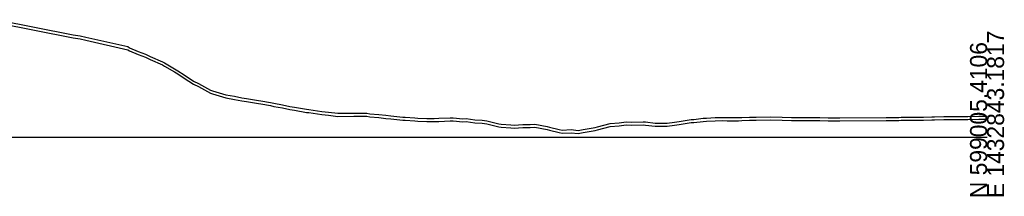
# Model space of a CAD drawing. Extents: x -26 to 2203, y -10 to 12201.
# Drawn here: x 440.9 to 602.8, y 9990.3 to 10019.3 of the extents above; entities that cross this region are included whole.
import ezdxf

# ---------------------------------------------------------------- set-up
doc = ezdxf.new("R2010")
doc.units = 0
for name, color, linetype in [('DESIGN - SHEET - Light Grid', 7, 'Continuous'), ('SURVEY - GROUND - Bottom of Topsoil Layer', 7, 'Continuous'), ('SURVEY - GROUND - Top of Ground', 7, 'Continuous')]:
    doc.layers.add(name, color=color, linetype=linetype)

msp = doc.modelspace()

# ---------------------------------------------------------------- linework, layer by layer
at = {"layer": 'DESIGN - SHEET - Light Grid'}
msp.add_line((300, 10000), (600, 10000), dxfattribs=at)
at = {"layer": 'SURVEY - GROUND - Bottom of Topsoil Layer'}
for p, q in [((437.07, 10018.78), (449.69, 10016.3)), ((449.69, 10016.3), (450.87, 10016.16)), ((450.87, 10016.16), (451.82, 10015.93)), ((451.82, 10015.93), (458.68, 10014.36)), ((458.68, 10014.36), (458.99, 10014.15)), ((458.99, 10014.15), (460.43, 10013.57)), ((460.43, 10013.57), (461.63, 10013.15)), ((461.63, 10013.15), (462.4, 10012.73)), ((462.4, 10012.73), (464.38, 10011.88)), ((464.38, 10011.88), (464.73, 10011.68)), ((464.73, 10011.68), (466.36, 10010.72)), ((466.36, 10010.72), (466.9, 10010.39)), ((466.9, 10010.39), (467.98, 10009.71)), ((467.98, 10009.71), (469.53, 10008.72)), ((469.53, 10008.72), (470.31, 10008.31)), ((470.31, 10008.31), (472.29, 10007.2)), ((472.29, 10007.2), (472.64, 10007.09)), ((472.64, 10007.09), (474.26, 10006.63)), ((474.26, 10006.63), (474.8, 10006.45)), ((474.8, 10006.45), (476.24, 10006.21)), ((476.24, 10006.21), (477.44, 10005.98)), ((477.44, 10005.98), (478.22, 10005.87)), ((478.22, 10005.87), (480.19, 10005.55)), ((480.19, 10005.55), (480.56, 10005.47)), ((480.56, 10005.47), (482.17, 10005.19)), ((482.17, 10005.19), (482.71, 10005.06)), ((482.71, 10005.06), (484.15, 10004.81)), ((484.15, 10004.81), (485.34, 10004.54)), ((485.34, 10004.54), (486.12, 10004.43)), ((486.12, 10004.43), (488.1, 10004.08)), ((488.1, 10004.08), (488.47, 10004.03)), ((488.47, 10004.03), (490.61, 10003.73)), ((490.61, 10003.73), (491.68, 10003.6)), ((491.68, 10003.6), (493.25, 10003.42)), ((493.25, 10003.42), (495.88, 10003.46)), ((495.88, 10003.46), (496.38, 10003.46)), ((496.38, 10003.46), (497.99, 10003.43)), ((497.99, 10003.43), (498.52, 10003.36)), ((498.52, 10003.36), (499.96, 10003.21)), ((499.96, 10003.21), (501.15, 10003.09)), ((501.15, 10003.09), (501.94, 10003)), ((501.94, 10003), (503.92, 10002.79)), ((503.92, 10002.79), (504.3, 10002.77)), ((504.3, 10002.77), (505.89, 10002.67)), ((505.89, 10002.67), (506.42, 10002.64)), ((506.42, 10002.64), (507.87, 10002.56)), ((507.87, 10002.56), (509.06, 10002.59)), ((509.06, 10002.59), (509.85, 10002.6)), ((509.85, 10002.6), (511.69, 10002.7)), ((511.69, 10002.7), (512.21, 10002.67)), ((512.21, 10002.67), (513.8, 10002.51)), ((513.8, 10002.51), (514.33, 10002.56)), ((514.33, 10002.56), (515.78, 10002.36)), ((515.78, 10002.36), (516.96, 10002.31)), ((516.96, 10002.31), (517.75, 10002.2)), ((517.75, 10002.2), (519.73, 10001.68)), ((538.05, 10001.74), (539.5, 10001.88)), ((539.5, 10001.88), (540.68, 10002.03)), ((540.68, 10002.03), (541.48, 10001.97)), ((541.48, 10001.97), (543.45, 10002.02)), ((543.45, 10002.02), (543.86, 10002)), ((543.86, 10002), (545.43, 10001.79)), ((545.43, 10001.79), (545.95, 10001.83)), ((545.95, 10001.83), (547.41, 10001.79)), ((547.41, 10001.79), (548.59, 10001.98)), ((548.59, 10001.98), (549.38, 10002.08)), ((549.38, 10002.08), (551.36, 10002.39)), ((551.36, 10002.39), (551.77, 10002.43)), ((551.77, 10002.43), (553.34, 10002.6)), ((553.34, 10002.6), (553.86, 10002.65)), ((553.86, 10002.65), (555.31, 10002.71)), ((555.31, 10002.71), (556.49, 10002.72)), ((556.49, 10002.72), (557.29, 10002.71)), ((557.29, 10002.71), (559.13, 10002.71)), ((559.13, 10002.71), (559.69, 10002.72)), ((559.69, 10002.72), (560.93, 10002.79)), ((560.93, 10002.79), (561.24, 10002.8)), ((561.24, 10002.8), (562.02, 10002.78)), ((562.02, 10002.78), (564.4, 10002.84)), ((564.4, 10002.84), (566.3, 10002.8)), ((566.3, 10002.8), (567.85, 10002.74)), ((567.85, 10002.74), (572.52, 10002.72)), ((572.52, 10002.72), (573.88, 10002.69)), ((573.88, 10002.69), (574.94, 10002.68)), ((574.94, 10002.68), (575.79, 10002.69)), ((575.79, 10002.69), (583.43, 10002.76)), ((583.43, 10002.76), (585.48, 10002.76)), ((585.48, 10002.76), (585.89, 10002.77)), ((585.89, 10002.77), (589.57, 10002.81)), ((589.57, 10002.81), (590.9, 10002.83)), ((590.9, 10002.83), (591.34, 10002.84)), ((591.34, 10002.84), (592.87, 10002.88)), ((592.87, 10002.88), (593.38, 10002.89)), ((593.38, 10002.89), (594.85, 10002.9)), ((594.85, 10002.9), (596.02, 10002.92)), ((596.02, 10002.92), (596.83, 10002.92)), ((596.83, 10002.92), (598.65, 10002.94)), ((598.65, 10002.94), (599.25, 10002.95)), ((599.25, 10002.95), (600, 10002.96)), ((519.73, 10001.68), (520.12, 10001.62)), ((520.12, 10001.62), (521.71, 10001.51)), ((521.71, 10001.51), (522.23, 10001.5)), ((522.23, 10001.5), (523.68, 10001.57)), ((523.68, 10001.57), (524.87, 10001.59)), ((524.87, 10001.59), (525.66, 10001.62)), ((525.66, 10001.62), (527.64, 10001.27)), ((527.64, 10001.27), (528.03, 10001.17)), ((528.03, 10001.17), (529.61, 10000.79)), ((529.61, 10000.79), (530.14, 10000.64)), ((530.14, 10000.64), (531.59, 10000.74)), ((531.59, 10000.74), (532.78, 10000.62)), ((532.78, 10000.62), (533.57, 10000.75)), ((533.57, 10000.75), (535.54, 10001.09)), ((535.54, 10001.09), (535.95, 10001.21)), ((535.95, 10001.21), (538.05, 10001.74))]:
    msp.add_line(p, q, dxfattribs=at)
at = {"layer": 'SURVEY - GROUND - Top of Ground'}
for p, q in [((437.07, 10019.28), (449.69, 10016.8)), ((449.69, 10016.8), (450.87, 10016.66)), ((450.87, 10016.66), (451.82, 10016.43)), ((451.82, 10016.43), (458.68, 10014.86)), ((458.68, 10014.86), (458.99, 10014.65)), ((458.99, 10014.65), (460.43, 10014.07)), ((460.43, 10014.07), (461.63, 10013.65)), ((461.63, 10013.65), (462.4, 10013.23)), ((462.4, 10013.23), (464.38, 10012.38)), ((464.38, 10012.38), (464.73, 10012.18)), ((464.73, 10012.18), (466.36, 10011.22)), ((466.36, 10011.22), (466.9, 10010.89)), ((466.9, 10010.89), (467.98, 10010.21)), ((467.98, 10010.21), (469.53, 10009.22)), ((469.53, 10009.22), (470.31, 10008.81)), ((470.31, 10008.81), (472.29, 10007.7)), ((472.29, 10007.7), (472.64, 10007.59)), ((472.64, 10007.59), (474.26, 10007.13)), ((474.26, 10007.13), (474.8, 10006.95)), ((474.8, 10006.95), (476.24, 10006.71)), ((476.24, 10006.71), (477.44, 10006.48)), ((477.44, 10006.48), (478.22, 10006.37)), ((478.22, 10006.37), (480.19, 10006.05)), ((480.19, 10006.05), (480.56, 10005.97)), ((480.56, 10005.97), (482.17, 10005.69)), ((482.17, 10005.69), (482.71, 10005.56)), ((482.71, 10005.56), (484.15, 10005.31)), ((484.15, 10005.31), (485.34, 10005.04)), ((485.34, 10005.04), (486.12, 10004.93)), ((486.12, 10004.93), (488.1, 10004.58)), ((488.1, 10004.58), (488.47, 10004.53)), ((488.47, 10004.53), (490.61, 10004.23)), ((490.61, 10004.23), (491.68, 10004.1)), ((491.68, 10004.1), (493.25, 10003.92)), ((493.25, 10003.92), (495.88, 10003.96)), ((495.88, 10003.96), (496.38, 10003.96)), ((496.38, 10003.96), (497.99, 10003.93)), ((497.99, 10003.93), (498.52, 10003.86)), ((498.52, 10003.86), (499.96, 10003.71)), ((499.96, 10003.71), (501.15, 10003.59)), ((501.15, 10003.59), (501.94, 10003.5)), ((501.94, 10003.5), (503.92, 10003.29)), ((591.34, 10003.34), (592.87, 10003.38)), ((592.87, 10003.38), (593.38, 10003.39)), ((593.38, 10003.39), (594.85, 10003.4)), ((594.85, 10003.4), (596.02, 10003.42)), ((596.02, 10003.42), (596.83, 10003.42)), ((596.83, 10003.42), (598.65, 10003.44)), ((598.65, 10003.44), (599.25, 10003.45)), ((599.25, 10003.45), (600, 10003.46)), ((503.92, 10003.29), (504.3, 10003.27)), ((504.3, 10003.27), (505.89, 10003.17)), ((505.89, 10003.17), (506.42, 10003.14)), ((506.42, 10003.14), (507.87, 10003.06)), ((507.87, 10003.06), (509.06, 10003.09)), ((509.06, 10003.09), (509.85, 10003.1)), ((509.85, 10003.1), (511.69, 10003.2)), ((511.69, 10003.2), (512.21, 10003.17)), ((512.21, 10003.17), (513.8, 10003.01)), ((513.8, 10003.01), (514.33, 10003.06)), ((514.33, 10003.06), (515.78, 10002.86)), ((515.78, 10002.86), (516.96, 10002.81)), ((516.96, 10002.81), (517.75, 10002.7)), ((517.75, 10002.7), (519.73, 10002.18)), ((519.73, 10002.18), (520.12, 10002.12)), ((520.12, 10002.12), (521.71, 10002.01)), ((521.71, 10002.01), (522.23, 10002)), ((522.23, 10002), (523.68, 10002.07)), ((523.68, 10002.07), (524.87, 10002.09)), ((524.87, 10002.09), (525.66, 10002.12)), ((525.66, 10002.12), (527.64, 10001.77)), ((527.64, 10001.77), (528.03, 10001.67)), ((535.95, 10001.71), (538.05, 10002.24)), ((538.05, 10002.24), (539.5, 10002.38)), ((539.5, 10002.38), (540.68, 10002.53)), ((540.68, 10002.53), (541.48, 10002.47)), ((541.48, 10002.47), (543.45, 10002.52)), ((543.45, 10002.52), (543.86, 10002.5)), ((543.86, 10002.5), (545.43, 10002.29)), ((545.43, 10002.29), (545.95, 10002.33)), ((545.95, 10002.33), (547.41, 10002.29)), ((547.41, 10002.29), (548.59, 10002.48)), ((548.59, 10002.48), (549.38, 10002.58)), ((549.38, 10002.58), (551.36, 10002.89)), ((551.36, 10002.89), (551.77, 10002.93)), ((551.77, 10002.93), (553.34, 10003.1)), ((553.34, 10003.1), (553.86, 10003.15)), ((553.86, 10003.15), (555.31, 10003.21)), ((555.31, 10003.21), (556.49, 10003.22)), ((556.49, 10003.22), (557.29, 10003.21)), ((557.29, 10003.21), (559.13, 10003.21)), ((559.13, 10003.21), (559.69, 10003.22)), ((559.69, 10003.22), (560.93, 10003.29)), ((560.93, 10003.29), (561.24, 10003.3)), ((561.24, 10003.3), (562.02, 10003.28)), ((562.02, 10003.28), (564.4, 10003.34)), ((564.4, 10003.34), (566.3, 10003.3)), ((566.3, 10003.3), (567.85, 10003.24)), ((567.85, 10003.24), (572.52, 10003.22)), ((572.52, 10003.22), (573.88, 10003.19)), ((573.88, 10003.19), (574.94, 10003.18)), ((574.94, 10003.18), (575.79, 10003.19)), ((575.79, 10003.19), (583.43, 10003.26)), ((583.43, 10003.26), (585.48, 10003.26)), ((585.48, 10003.26), (585.89, 10003.27)), ((585.89, 10003.27), (589.57, 10003.31)), ((589.57, 10003.31), (590.9, 10003.33)), ((590.9, 10003.33), (591.34, 10003.34)), ((528.03, 10001.67), (529.61, 10001.29)), ((529.61, 10001.29), (530.14, 10001.14)), ((530.14, 10001.14), (531.59, 10001.24)), ((531.59, 10001.24), (532.78, 10001.12)), ((532.78, 10001.12), (533.57, 10001.25)), ((533.57, 10001.25), (535.54, 10001.59)), ((535.54, 10001.59), (535.95, 10001.71))]:
    msp.add_line(p, q, dxfattribs=at)

# ---------------------------------------------------------------- texts
at = {"layer": 'DESIGN - SHEET - Light Grid'}
for s, p in [('E 1432843.1817', (602.8, 9990)), ('N 599005.4106', (600, 9990))]:
    msp.add_text(s, height=2.8, rotation=90, dxfattribs=at).set_placement(p)

doc.saveas('drawing.dxf')
